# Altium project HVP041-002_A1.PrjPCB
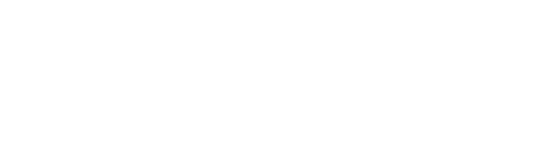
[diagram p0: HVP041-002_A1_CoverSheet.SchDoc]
4 sheets, 106 parts. Net scope: global (net labels, ports and power ports of the same name join across sheets).
Board file: HVP041-002_A1.PcbDoc
Sheets:
  HVP041-002_A1_CoverSheet.SchDoc
  HVP041-002_A1_DC.SchDoc
  HVP041-002_A1_Footprint.SchDoc
  HVP041-002_A1_Hardware.SchDoc

## Sheet HVP041-002_A1_CoverSheet.SchDoc
size 431 x 279 mm; Date: Not shown in title block; ApprovedBy: Not shown in title block; CheckedBy: Not shown in title block; Author: Not shown in title block; CompanyName: Not shown in title block; Engineer: Not shown in title block; Organization: Not shown in title block; Address1: Not shown in title block; Address2: Not shown in title block; Address3: Not shown in title block; Address4: Not shown in title block; DocumentNumber: 1; Revision: Use project parameter SCH_Rev; SheetNumber: 2; SheetTotal: 3; PageSetup: Record=PageOptions¦CenterHorizontal=True¦CenterVertical=True¦PrintScale=1.00¦XCorrection=1.00¦YCorrection=1.00¦PrintKind=0¦BorderSize=5000000¦LeftOffset=0¦BottomOffset=0¦Orientation=2¦PaperLength=1000¦PaperWidth=1000¦Scale=100¦PaperSource=15¦PrintQuality=600¦MediaType=1¦DitherType=10¦PaperKind=Letter¦PrintScaleMode=1

## Sheet HVP041-002_A1_DC.SchDoc
size A2; PageSetup: Record=PageOptions¦CenterHorizontal=True¦CenterVertical=True¦PrintScale=0.69¦XCorrection=1.00¦YCorrection=1.00¦PrintKind=0¦BorderSize=5000000¦LeftOffset=0¦BottomOffset=0¦Orientation=2¦PaperLength=1000¦PaperWidth=1000¦Scale=100¦PaperSource=15¦PrintQuality=600¦MediaType=1¦DitherType=10¦PaperKind=Letter¦PrintScaleMode=1
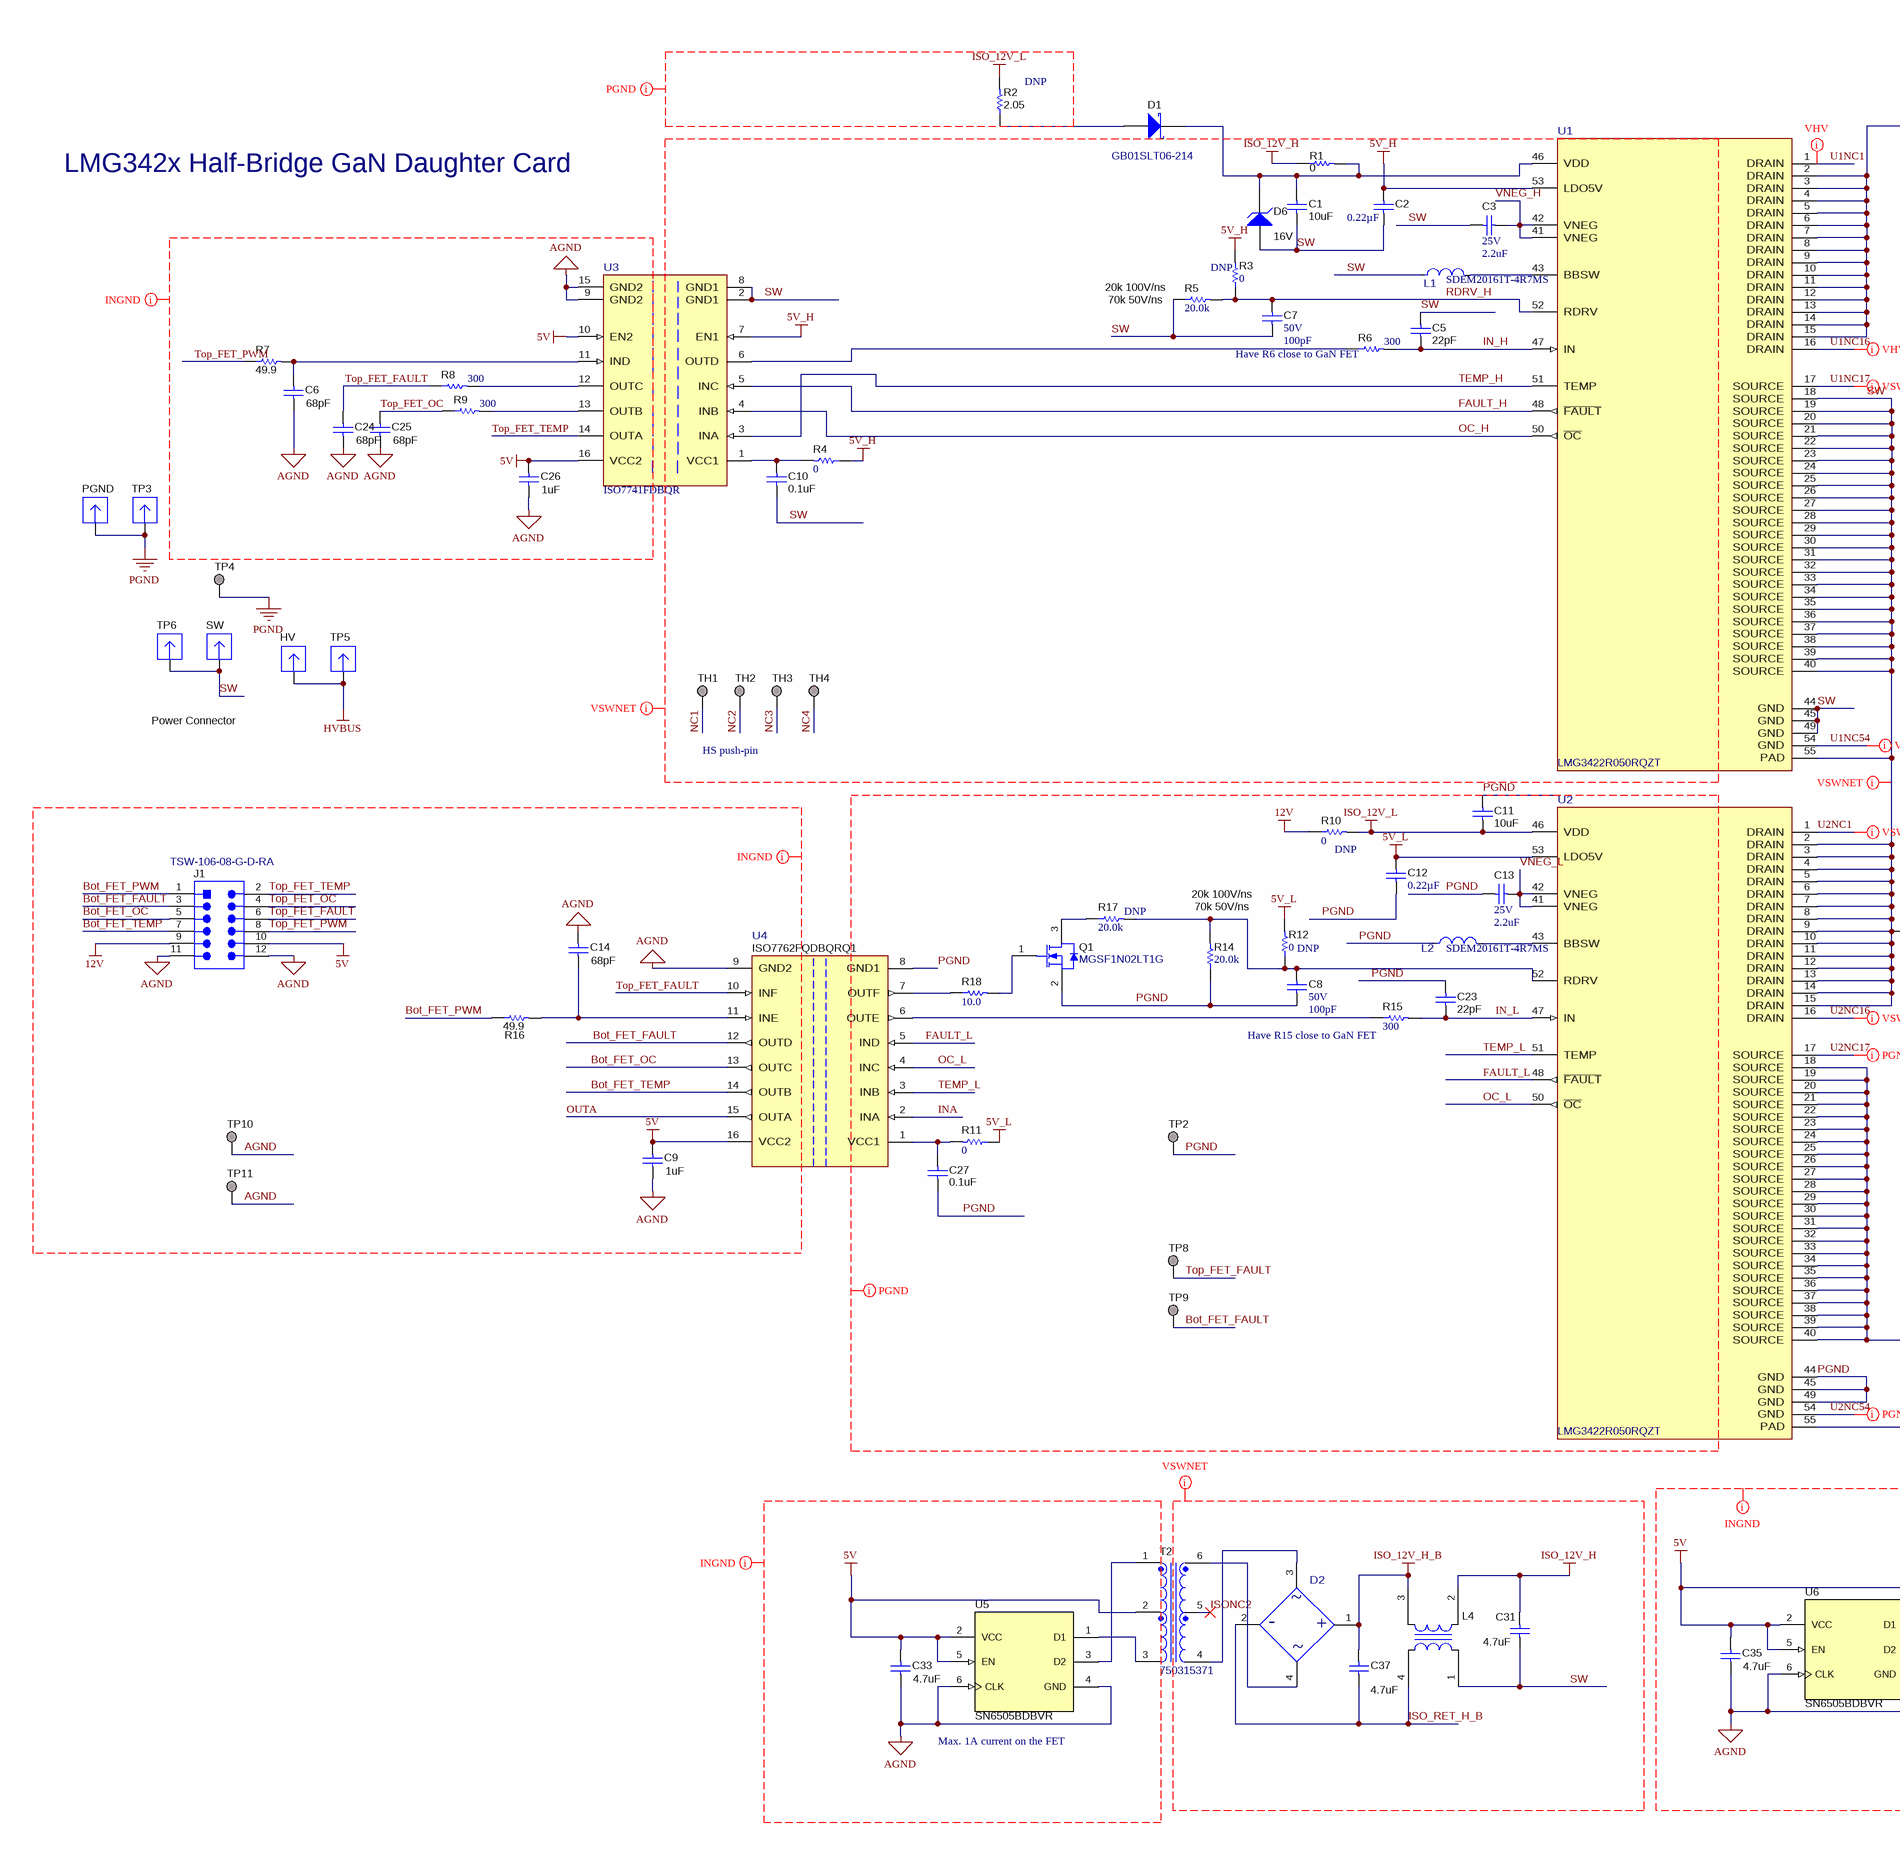
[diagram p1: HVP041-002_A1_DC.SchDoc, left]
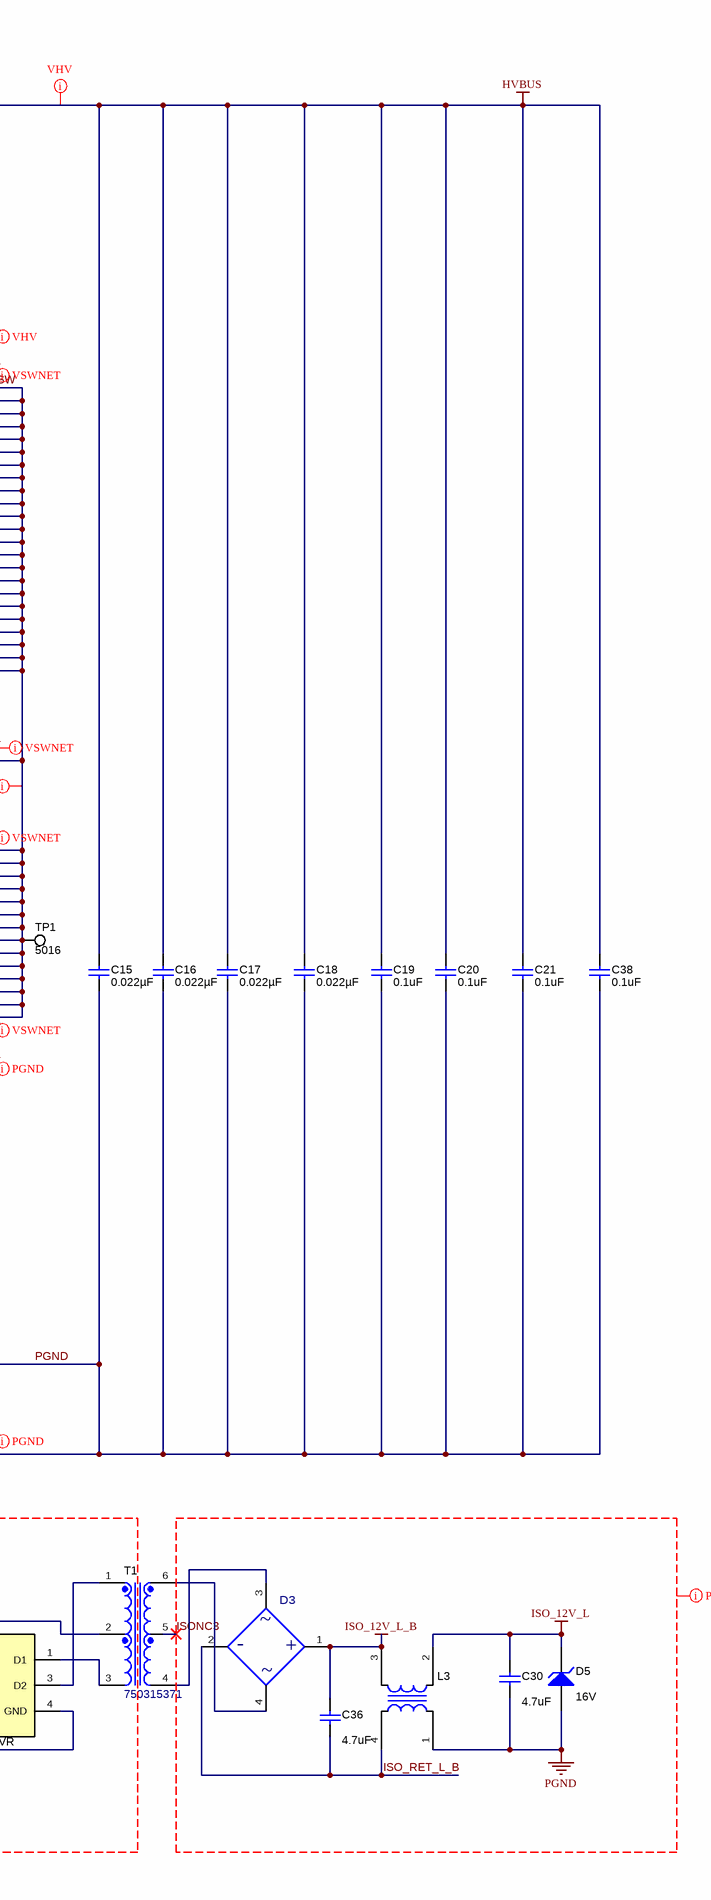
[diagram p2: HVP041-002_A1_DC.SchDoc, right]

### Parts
C1  ValueDisplayed: 10uF  [1206_190]  (hidden comment: C1206C106K3RACTU)
C2  ValueDisplayed: 0.22µF  [0402]  (hidden comment: CL05B224KO5NNNC)
C3  VDC_V: 25V  ValueDisplayed: 2.2uF  [0805_HV]  (hidden comment: GRM219R61E225KA12D)
C5  ValueDisplayed: 22pF  [0402]  (hidden comment: C1005C0G1H220J050BA)
C6  ValueDisplayed: 68pF  [0402]  (hidden comment: C1005C0G1H680J050BA)
C7  VDC_V: 50V  ValueDisplayed: 100pF  [0402]  (hidden comment: 04025A101FAT2A)
C8  VDC_V: 50V  ValueDisplayed: 100pF  [0402]  (hidden comment: 04025A101FAT2A)
C9  ValueDisplayed: 1uF  [0402]  (hidden comment: C1005X5R1E105K050BC)
C10  ValueDisplayed: 0.1uF  [0402]  (hidden comment: C1005X7R1H104K050BB)
C11  ValueDisplayed: 10uF  [1206_190]  (hidden comment: C1206C106K3RACTU)
C12  ValueDisplayed: 0.22µF  [0402]  (hidden comment: CL05B224KO5NNNC)
C13  VDC_V: 25V  ValueDisplayed: 2.2uF  [0805_HV]  (hidden comment: GRM219R61E225KA12D)
C14  ValueDisplayed: 68pF  [0402]  (hidden comment: C1005C0G1H680J050BA)
C15  ValueDisplayed: 0.022µF  [1206_190]  (hidden comment: C1206C223KDRACTU)
C16  ValueDisplayed: 0.022µF  [1206_190]  (hidden comment: C1206C223KDRACTU)
C17  ValueDisplayed: 0.022µF  [1206_190]  (hidden comment: C1206C223KDRACTU)
C18  ValueDisplayed: 0.022µF  [1206_190]  (hidden comment: C1206C223KDRACTU)
C19  ValueDisplayed: 0.1uF  [1812_254]  (hidden comment: C1812W104KDRACTU)
C20  ValueDisplayed: 0.1uF  [1812_254]  (hidden comment: C1812W104KDRACTU)
C21  ValueDisplayed: 0.1uF  [1812_254]  (hidden comment: C1812W104KDRACTU)
C23  ValueDisplayed: 22pF  [0402]  (hidden comment: C1005C0G1H220J050BA)
C24  ValueDisplayed: 68pF  [0402]  (hidden comment: C1005C0G1H680J050BA)
C25  ValueDisplayed: 68pF  [0402]  (hidden comment: C1005C0G1H680J050BA)
C26  ValueDisplayed: 1uF  [0402]  (hidden comment: C1005X5R1E105K050BC)
C27  ValueDisplayed: 0.1uF  [0402]  (hidden comment: C1005X7R1H104K050BB)
C30  ValueDisplayed: 4.7uF  [0603]  (hidden comment: C1608X5R1V475K080AC)
C31  ValueDisplayed: 4.7uF  [0603]  (hidden comment: C1608X5R1V475K080AC)
C33  ValueDisplayed: 4.7uF  [0805_HV]  (hidden comment: GCM21BR71C475KA73L)
C35  ValueDisplayed: 4.7uF  [0805_HV]  (hidden comment: GCM21BR71C475KA73L)
C36  ValueDisplayed: 4.7uF  [0603]  (hidden comment: C1608X5R1V475K080AC)
C37  ValueDisplayed: 4.7uF  [0603]  (hidden comment: C1608X5R1V475K080AC)
C38  ValueDisplayed: 0.1uF  [1812_254]  (hidden comment: C1812W104KDRACTU)
D1  GB01SLT06-214  [SMB]
D2  KMB23STR  [FP-KMB23STR_SMT_4MM725_3MM85-MFG]  (value not drawn)
D3  KMB23STR  [FP-KMB23STR_SMT_4MM725_3MM85-MFG]  (value not drawn)
D5  value 16V  [SOD-123]  (hidden comment: BZT52C16-7-F)
D6  value 16V  [SOD-123]  (hidden comment: BZT52C16-7-F)
HV  3621-0-32-15-00-00-08-0  [Mill-Max_3621-0-32-xx-00-00-08-0]  (value not drawn)
J1  TSW-106-08-G-D-RA  [AB12-DEST]
L1  SDEM20161T-4R7MS  [FP-SDEM20161T-4R7MS_SMD2-MFG]  (value not drawn)
L2  SDEM20161T-4R7MS  [FP-SDEM20161T-4R7MS_SMD2-MFG]  (value not drawn)
L3  ACM2520-601-2P-T002  [TDK_ACM2520-2P]  (value not drawn)
L4  ACM2520-601-2P-T002  [TDK_ACM2520-2P]  (value not drawn)
PGND  3621-0-32-15-00-00-08-0  [Mill-Max_3621-0-32-xx-00-00-08-0]  (value not drawn)
Q1  MGSF1N02LT1G  [SOT-23]
R1  ValueDisplayed: 0  [0603]  (hidden comment: MCT06030Z0000ZP500)
R2  ValueDisplayed: 2.05  [1206]  (hidden comment: CRCW12062R05FKEA)
R3  ValueDisplayed: 0  [0402]  (hidden comment: MCR01MZPJ000)  (no BOM)
R4  ValueDisplayed: 0  [0402]  (hidden comment: MCR01MZPJ000)
R5  ValueDisplayed: 20.0k  [0402]  (hidden comment: CRCW040220K0FKED)
R6  ValueDisplayed: 300  [0402]  (hidden comment: CRCW0402300RJNED)
R7  ValueDisplayed: 49.9  [0402]  (hidden comment: RC0402FR-0749R9L)
R8  ValueDisplayed: 300  [0402]  (hidden comment: CRCW0402300RJNED)
R9  ValueDisplayed: 300  [0402]  (hidden comment: CRCW0402300RJNED)
R10  ValueDisplayed: 0  [1206]  (hidden comment: ERJ-8GEY0R00V)  (no BOM)
R11  ValueDisplayed: 0  [0402]  (hidden comment: MCR01MZPJ000)
R12  ValueDisplayed: 0  [0402]  (hidden comment: MCR01MZPJ000)  (no BOM)
R14  ValueDisplayed: 20.0k  [0402]  (hidden comment: CRCW040220K0FKED)
R15  ValueDisplayed: 300  [0402]  (hidden comment: CRCW0402300RJNED)
R16  ValueDisplayed: 49.9  [0402]  (hidden comment: RC0402FR-0749R9L)
R17  ValueDisplayed: 20.0k  [0402]  (hidden comment: CRCW040220K0FKED)  (no BOM)
R18  ValueDisplayed: 10.0  [0402]  (hidden comment: CRCW040210R0FKED)
SW  3621-0-32-15-00-00-08-0  [Mill-Max_3621-0-32-xx-00-00-08-0]  (value not drawn)
T1  750315371  [Wurth_750315371]
T2  750315371  [Wurth_750315371]
TH1  (no value)  [TP_H045P075]  (no BOM)
TH2  (no value)  [TP_H045P075]  (no BOM)
TH3  (no value)  [TP_H045P075]  (no BOM)
TH4  (no value)  [TP_H045P075]  (no BOM)
TP1  5016  [Testpoint_Keystone_Compact]
TP2  (no value)  [TESTPOINT]
TP3  3621-0-32-15-00-00-08-0  [Mill-Max_3621-0-32-xx-00-00-08-0]  (value not drawn)
TP4  (no value)  [Harwin_S2751-46R]
TP5  3621-0-32-15-00-00-08-0  [Mill-Max_3621-0-32-xx-00-00-08-0]  (value not drawn)
TP6  3621-0-32-15-00-00-08-0  [Mill-Max_3621-0-32-xx-00-00-08-0]  (value not drawn)
TP8  (no value)  [TESTPOINT]
TP9  (no value)  [TESTPOINT]
TP10  (no value)  [TESTPOINT]
TP11  (no value)  [TESTPOINT]
U1  LMG3422R050RQZT  [RQZ0054A-MFG-NV]
U2  LMG3422R050RQZT  [RQZ0054A-MFG-NV]
U3  ISO7741FDBQR  [DBQ0016A-MFG]
U4  ISO7762FQDBQRQ1  [DBQ0016A-MFG]
U5  SN6505BDBVR  [DBV0006A_N]
U6  SN6505BDBVR  [DBV0006A_N]

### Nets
5V: C9.1 C26.1 C33.1 C35.1 J1.10 T1.2 T2.2 U3.10(EN2) U3.16(VCC2) U4.16(VCC2) U5.2(VCC) U5.5(EN) U6.2(VCC) U6.5(EN)
5V_H: C2.1 R3.2 R4.1 U1.53(LDO5V) U3.7(EN1)
5V_L: C12.1 R11.1 R12.2 U2.53(LDO5V)
12V: J1.9 R10.1
AGND: C6.2 C9.2 C14.1 C24.2 C25.2 C26.2 C33.2 C35.2 J1.11 J1.12 TP10.1 TP11.1 U3.9(GND2) U3.15(GND2) U4.9(GND2) U5.4(GND) U5.6(CLK) U6.4(GND) U6.6(CLK)
HVBUS: C15.1 C16.1 C17.1 C18.1 C19.1 C20.1 C21.1 C38.1 HV.1 TP5.1 U1.2(DRAIN) U1.3(DRAIN) U1.4(DRAIN) U1.5(DRAIN) U1.6(DRAIN) U1.7(DRAIN) U1.8(DRAIN) U1.9(DRAIN) U1.10(DRAIN) U1.11(DRAIN) U1.12(DRAIN) U1.13(DRAIN) U1.14(DRAIN) U1.15(DRAIN)
ISO_12V_H: C31.1 L4.2 R1.1
ISO_12V_H_B: C37.1 D2.1(+) L4.3
ISO_12V_L: C11.2 C30.1 D5.1(K) L3.2 R2.2 R10.2 U2.46(VDD)
ISO_12V_L_B: C36.1 D3.1(+) L3.3
PGND: C8.2 C11.1 C12.2 C13.2 C15.2 C16.2 C17.2 C18.2 C19.2 C20.2 C21.2 C23.1 C27.2 C30.2 C38.2 D5.2(A) L2.1 L3.1 PGND.1 Q1.2(S) R14.1 TP2.1 TP3.1 TP4.1 U2.18(SOURCE) U2.19(SOURCE) U2.20(SOURCE) U2.21(SOURCE) U2.22(SOURCE) U2.23(SOURCE) U2.24(SOURCE) U2.25(SOURCE) U2.26(SOURCE) U2.27(SOURCE) U2.28(SOURCE) U2.29(SOURCE) U2.30(SOURCE) U2.31(SOURCE) U2.32(SOURCE) U2.33(SOURCE) U2.34(SOURCE) U2.35(SOURCE) U2.36(SOURCE) U2.37(SOURCE) U2.38(SOURCE) U2.39(SOURCE) U2.40(SOURCE) U2.44(GND) U2.45(GND) U2.49(GND) U2.55(PAD) U4.8(GND1)
Bot_FET_FAULT: J1.3 TP9.1 U4.12(OUTD)
Bot_FET_OC: J1.5 U4.13(OUTC)
Bot_FET_PWM: J1.1 R16.1
Bot_FET_TEMP: J1.7 U4.14(OUTB)
FAULT_H: U1.48(~{FAULT}) U3.5(INC)
FAULT_L: U2.48(~{FAULT}) U4.5(IND)
IN_H: C5.2 R6.2 U1.47(IN)
IN_L: C23.2 R15.2 U2.47(IN)
INA: U4.2(INA)
ISO_RET_H_B: C37.2 D2.2(-) L4.4
ISO_RET_L_B: C36.2 D3.2(-) L3.4
ISONC2: T2.5
ISONC3: T1.5
NC1: TH1.1
NC2: TH2.1
NC3: TH3.1
NC4: TH4.1
OC_H: U1.50(~{OC}) U3.4(INB)
OC_L: U2.50(~{OC}) U4.4(INC)
OUTA: U4.15(OUTA)
RDRV_H: C7.1 R3.1 R5.2 U1.52(RDRV)
SW: C1.2 C2.2 C3.2 C5.1 C7.2 C10.2 C31.2 D6.2(A) L1.1 L4.1 R5.1 SW.1 TP1.1 TP6.1 U1.18(SOURCE) U1.19(SOURCE) U1.20(SOURCE) U1.21(SOURCE) U1.22(SOURCE) U1.23(SOURCE) U1.24(SOURCE) U1.25(SOURCE) U1.26(SOURCE) U1.27(SOURCE) U1.28(SOURCE) U1.29(SOURCE) U1.30(SOURCE) U1.31(SOURCE) U1.32(SOURCE) U1.33(SOURCE) U1.34(SOURCE) U1.35(SOURCE) U1.36(SOURCE) U1.37(SOURCE) U1.38(SOURCE) U1.39(SOURCE) U1.40(SOURCE) U1.44(GND) U1.45(GND) U1.49(GND) U1.55(PAD) U2.2(DRAIN) U2.3(DRAIN) U2.4(DRAIN) U2.5(DRAIN) U2.6(DRAIN) U2.7(DRAIN) U2.8(DRAIN) U2.9(DRAIN) U2.10(DRAIN) U2.11(DRAIN) U2.12(DRAIN) U2.13(DRAIN) U2.14(DRAIN) U2.15(DRAIN) U3.2(GND1) U3.8(GND1)
TEMP_H: U1.51(TEMP) U3.3(INA)
TEMP_L: U2.51(TEMP) U4.3(INB)
Top_FET_FAULT: C24.1 J1.6 R8.1 TP8.1 U4.10(INF)
Top_FET_OC: C25.1 J1.4 R9.1
Top_FET_PWM: J1.8 R7.1
Top_FET_TEMP: J1.2 U3.14(OUTA)
U1NC1: U1.1(DRAIN)
U1NC16: U1.16(DRAIN)
U1NC17: U1.17(SOURCE)
U1NC54: U1.54(GND)
U2NC1: U2.1(DRAIN)
U2NC16: U2.16(DRAIN)
U2NC17: U2.17(SOURCE)
U2NC54: U2.54(GND)
VNEG_H: C3.1 U1.41(VNEG) U1.42(VNEG)
VNEG_L: C13.1 U2.41(VNEG) U2.42(VNEG)
NetC1_1: C1.1 D1.1(K) D6.1(K) R1.2 U1.46(VDD)
NetC6_1: C6.1 R7.2 U3.11(IND)
NetC8_1: C8.1 R12.1 R14.2 R17.2 U2.52(RDRV)
NetC10_1: C10.1 R4.2 U3.1(VCC1)
NetC14_2: C14.2 R16.2 U4.11(INE)
NetC27_1: C27.1 R11.2 U4.1(VCC1)
NetD1_2: D1.2(A) R2.1
NetD2_3: D2.3(1_~) T2.4
NetD2_4: D2.4(2_~) T2.6
NetD3_3: D3.3(1_~) T1.4
NetD3_4: D3.4(2_~) T1.6
NetL1_2: L1.2 U1.43(BBSW)
NetL2_2: L2.2 U2.43(BBSW)
NetQ1_1: Q1.1(G) R18.2
NetQ1_3: Q1.3(D) R17.1
NetR6_1: R6.1 U3.6(OUTD)
NetR8_2: R8.2 U3.12(OUTC)
NetR9_2: R9.2 U3.13(OUTB)
NetR15_1: R15.1 U4.6(OUTE)
NetR18_1: R18.1 U4.7(OUTF)
NetT1_1: T1.1 U6.3(D2)
NetT1_3: T1.3 U6.1(D1)
NetT2_1: T2.1 U5.3(D2)
NetT2_3: T2.3 U5.1(D1)

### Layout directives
net class VSWNET: 5V_H, FAULT_H, IN_H, ISO_12V_H, ISO_12V_H_B, ISO_RET_H_B, ISONC2, NC1, NC2, NC3, NC4, OC_H, RDRV_H, SW, TEMP_H, U1NC17, U1NC54, U2NC1, U2NC16, VNEG_H
net class VHV: HVBUS, U1NC1, U1NC16
net class INGND: 5V, 12V, AGND, Bot_FET_FAULT, Bot_FET_OC, Bot_FET_PWM, Bot_FET_TEMP, OUTA, Top_FET_FAULT, Top_FET_OC, Top_FET_PWM, Top_FET_TEMP
net class PGND: 5V_L, 12V, Bot_FET_FAULT, FAULT_L, IN_L, INA, ISO_12V_L, ISO_12V_L_B, ISO_RET_L_B, ISONC3, OC_L, PGND, TEMP_L, Top_FET_FAULT, U2NC17, U2NC54, VNEG_L

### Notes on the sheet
- (near R2) DNP
- LMG342x Half-Bridge GaN Daughter Card
- (near R5) 20k 100V/ns
- (near R5) 70k 50V/ns
- (near R3) DNP
- (near L1) SDEM20161T-4R7MS
- (near R6) Have R6 close to GaN FET
- Power Connector
- HS push-pin
- (near R10) DNP
- (near R17) DNP
- 20k 100V/ns
- 70k 50V/ns
- (near R12) DNP
- (near L2) SDEM20161T-4R7MS
- (near R15) Have R15 close to GaN FET
- Max. 1A current on the FET

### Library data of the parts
C1 C11 = CMP-0008589-2: CAP, CERM, 10 uF, 25 V, +/- 10%, X7R, 1206_190; Manufacturer: Kemet; Polarized: N; Value: 10uF; U/M: EA; Cap_F: 10µF; Value1: Unknown; VDC_V: 25V; TaMin_C: -55°C; TaMax_C: 125°C; Cap_Case: 1206; SizeArea_mm2: 5.12; SizeAreaWB_mm2: 10.92; SizeX_mm: 3.2; SizeY_mm: 1.6; SizeZ_mm: 1.9; AEC Category: Q200
C2 C12 = CMP-0860563-1: CAP, CERM, 0.22 µF, 16 V,+/- 10%, X7R, 0402; Manufacturer: Samsung Electro-Mechanics; SizeX_mm: 1; Green_REACh: Incomplete; TaMin_C: -55°C; SizeArea_mm2: 0.5; TaMax_C: 125°C; U/M: EA; Green_Lifecycle: Active; SizeAreaWB_mm2: 3; VDC_V: 16V; AEC Qualified: N; SizeZ_mm: 0.6; AEC Category: Q200; Cap_F: 220nF; Value: 0.22uF
C3 C13 = CMP-0008208-1: CAP, CERM, 2.2 uF, 25 V, +/- 10%, X5R, 0805; Manufacturer: MuRata; TaMin_C: -55°C; ESR_ohm: 6m; Polarized: N; SizeAreaWB_mm2: 6.75; Value1: 0.006 ohm; U/M: EA; Value: 2.2uF; TaMax_C: 85°C; SizeZ_mm: 1.45; SizeX_mm: 2; SizeY_mm: 1.25; Cap_Case: 0805; SizeArea_mm2: 2.5; Cap_F: 2.2µF; AEC Category: Q200
C5 C23 = CMP-0006248-2: CAP, CERM, 22 pF, 50 V, +/- 5%, C0G/NP0, 0402; Manufacturer: TDK; Alternate PartNumber: CGA2B2NP01H220J050BA; Polarized: N; Value: 22pF; U/M: EA; Value1: Unknown; VDC_V: 50V; TaMin_C: -55°C; TaMax_C: 125°C; AEC Category: Q200; SizeArea_mm2: 0.5; SizeAreaWB_mm2: 3; SizeX_mm: 1; SizeZ_mm: 0.6
C6 C14 C24 C25 = CMP-0006251-2: CAP, CERM, 68 pF, 50 V, +/- 5%, C0G/NP0, 0402; Manufacturer: TDK; Alternate Manufacturer: Murata; Alternate PartNumber: GRM1555C1H680JA01D; TaMin_C: -55°C; Polarized: N; SizeAreaWB_mm2: 3; Value1: Unknown; U/M: EA; Value: 68pF; TaMax_C: 125°C; SizeZ_mm: 0.6; SizeX_mm: 1; SizeY_mm: 0.5; Value2: 50V; AEC Category: Q200
C7 C8 = CMP-0006196-2: CAP, CERM, 100 pF, 50 V, +/- 1%, C0G/NP0, 0402; Manufacturer: AVX; TaMin_C: -55°C; Polarized: N; SizeAreaWB_mm2: 3; Value1: Unknown; U/M: EA; Value: 100pF; TaMax_C: 125°C; SizeZ_mm: 0.6; SizeX_mm: 1; SizeY_mm: 0.5; AEC Category: Q200
C9 C26 = CMP-0006276-2: CAP, CERM, 1 uF, 25 V, +/- 10%, X5R, 0402; Manufacturer: TDK; Alternate PartNumber: C1005X5R1E225K050BC; TaMin_C: -55°C; Polarized: N; SizeAreaWB_mm2: 3; Value1: Unknown; U/M: EA; Value: 1uF; TaMax_C: 80°C; SizeZ_mm: 0.6; SizeX_mm: 1; SizeY_mm: 0.5; Value2: 25V; CompType: Capacitor; Cap_F: 1µF; AEC Category: Q200
C10 C27 = CMP-0006297-2: CAP, CERM, 0.1 uF, 50 V, +/- 10%, X7R, 0402; Manufacturer: TDK; Alternate PartNumber: 885012205037; Alternate Manufacturer: Wurth Elektronik; Polarized: N; Value: 0.1uF; U/M: EA; Cap_F: 100nF; ESR_ohm: 0.039064; Value1: 0.039064 ohm; VDC_V: 50V; IRMS_A: 8.14669dA; TaMin_C: -55°C; TaMax_C: 125°C; SizeArea_mm2: 0.5; SizeAreaWB_mm2: 3; SizeX_mm: 1; SizeZ_mm: 0.6; AEC Category: Q200
C15-C18 = CMP-0084048-1: CAP, CERM, 0.022 µF, 1000 V,+/- 10%, X7R, AEC-Q200 Grade 1, 1206; Manufacturer: Kemet; Polarized: N; CompType: Capacitor; Value: 0.022uF; U/M: EA; Cap_F: 22nF; VDC_V: 1kV; Value2: 1000V; TaMin_C: -55°C; TaMax_C: 125°C; Cap_Case: 1206; SizeArea_mm2: 5.12; SizeAreaWB_mm2: 10.92; SizeX_mm: 3.2; SizeY_mm: 1.6; SizeZ_mm: 1.9; AEC Category: Q200; AEC Qualified: Y; AEC Grade: 1
C19-C21 C38 = CMP-0009326-2: CAP, CERM, 0.1 uF, 1000 V, +/- 10%, X7R, 1812; Manufacturer: Kemet; Polarized: N; Value: 0.1uF; U/M: EA; Cap_F: 100nF; Value1: Unknown; VDC_V: 1kV; Value2: 1000V; TaMin_C: -55°C; TaMax_C: 125°C; Cap_Case: 1812; AEC Category: Q200; SizeArea_mm2: 14.4; SizeAreaWB_mm2: 23.1; SizeX_mm: 4.5; SizeY_mm: 3.2; SizeZ_mm: 2.54
C30 C31 C36 = CMP-0007022-5: CAP, CERM, 4.7 uF, 35 V, +/- 10%, X5R, 0603; Manufacturer: TDK; TaMin_C: -55°C; ESR_ohm: 3.728m; Polarized: N; SizeAreaWB_mm2: 4.68; Value1: 0.003728 ohm; U/M: EA; Value: 4.7uF; TaMax_C: 85°C; SizeZ_mm: 1; SizeX_mm: 1.6; SizeY_mm: 0.8; Value2: 35V; SizeArea_mm2: 1.28; Cap_F: 4.7µF; IRMS_A: 2.69359A; AEC Category: Q200
C33 C35 = CMP-0008020-2: CAP, CERM, 4.7 uF, 16 V, +/- 10%, X7R, AEC-Q200 Grade 1, 0805; Manufacturer: MuRata; TaMin_C: -55°C; Polarized: N; SizeAreaWB_mm2: 6.75; Value1: Unknown; U/M: EA; Value: 4.7uF; TaMax_C: 125°C; SizeZ_mm: 1.45; SizeX_mm: 2; SizeY_mm: 1.25; Cap_Case: 0805; Value2: 16V; SizeArea_mm2: 2.5; AEC Qualified: Y; Cap_F: 4.7µF; AEC Grade: 1; AEC Category: Q200
C37 = CMP-0007022-5: CAP, CERM, 4.7 uF, 35 V, +/- 10%, X5R, 0603; Manufacturer: TDK; TaMin_C: -55°C; ESR_ohm: 3.728m; Polarized: N; SizeAreaWB_mm2: 4.68; Value1: 0.003728 ohm; U/M: EA; Value: 4.7uF; TaMax_C: 85°C; SizeZ_mm: 1; SizeX_mm: 1.6; SizeY_mm: 0.8; Value2: 35V; SizeArea_mm2: 1.28; CompType: Capacitor; Cap_F: 4.7µF; IRMS_A: 2.69359A; AEC Category: Q200
D1 = CMP-0076998-2: Diode, Schottky, 650 V, 1 A, SMB; Manufacturer: GeneSiC Semiconductor; Value1: 1A; SizeZ_mm: 2.6; Value: 650V; SizeAreaWB_mm2: 44.156; TJmax_C: 175°C; RJC_CperW: 3.55; SizeArea_mm2: 21.336; AEC Category: Q101; Value2: 2V; SizeY_mm: 3.81; SizeX_mm: 5.6
D2 D3 = CMP-0089345-2: Bridge Rectifier Single Phase Schottky 30V Surface Mount MBS; Manufacturer: SMC; TJmax_C: 150°C; Cap_F: 28pF; Max Surge Forward Current: 50A; Forward Current: 2A; Peak Reverse Current: 0.1mA; CompType: Diode; Standoff Height: 0.2mm; AEC Category: Q101; SizeZ_mm: 2.9mm; AEC Qualified: No
D5 D6 = CMP-0005769-2: Diode, Zener, 16 V, 500 mW, AEC-Q101, SOD-123; Manufacturer: Diodes Inc.; Power_W: 500mW; SizeAreaWB_mm2: 13.095; Value1: 0.5W; RJA_CperW: 338; U/M: EA; SizeZ_mm: 1.35; SizeX_mm: 3.85; SizeY_mm: 1.7; SizeArea_mm2: 6.545; AEC Qualified: Y; AEC Category: Q101
HV PGND SW TP3 TP5 TP6 = CMP-0082316-1: Manufacturer: Mill-Max; CompType: PCB Pin; ContactFinish: Gold; Gender: Male; Row_Count: 1
J1 = CMP-0075414-2: Header, 100mil, 6x2, Gold, R/A, TH; Manufacturer: Samtec; Pitch_mm: 2.54; Cert_VDE: N; Gender: Male; Cert_CSA: Y; Current_A: 6.3A; Voltage_V: 550V; Row_Count: 2
L1 L2 = CMP-0089347-1: 4.7µH Unshielded Inductor 1.1A 426mOhm Max 0806 (2016 Metric); Manufacturer: Cyntec; AEC Qualified: No; Material: Metal Dust; Isat: 1.26A; Test Frequency: 1MHz; DCR_ohm: 0.426; SizeZ_mm: 1mm; Tolerance_%: 20%
L3 L4 = CMP-0013161-2: Coupled inductor, 0.2 A, 0.45 ohm, SMD; Manufacturer: TDK; DCR_ohm: 4.5d; SizeAreaWB_mm2: 10.5; SizeArea_mm2: 5; SizeX_mm: 2.5; SizeY_mm: 2; SizeZ_mm: 1.3
Q1 = CMP-0000221-1: MOSFET, N-CH, 20 V, 0.75 A, SOT-23; Alternate Manufacturer: None; Manufacturer: ON Semiconductor; SizeZ_mm: 1.1; ChType: N; Value2: 6 nC; Value1: 0.1; VdsMax_V: 20V; SizeX_mm: 2.5; SizeY_mm: 3; Value: 20V; Rdson45_ohm: 0.13; SizeArea_mm2: 7.5; AEC Category: Q101; IdsMax_A: 750mA; SizeAreaWB_mm2: 14; U/M: EA; QgTyp_nC: 6
R1 = CMP-0025884-3: RES, 0, 5%, 0.125 W, 0603; Manufacturer: Vishay/Beyschlag; Power_W: 125mW; TempCo: ppm/C; Value_Code: 0000; U/M: EA; Value: 0; EIA_Code: E24; SizeX_mm: 1.6; SizeY_mm: 0.8; SizeZ_mm: 1; Value2: 0.125W; SizeArea_mm2: 1.28; CompType: Resistor; AEC Qualified: N; AEC Category: Q200
R2 = CMP-0016879-3: RES, 2.05, 1%, 0.25 W, AEC-Q200 Grade 0, 1206; Manufacturer: Vishay-Dale; Power_W: 250mW; TempCo: 100 ppm/C; Value_Code: 2R05; Value: 2.05; EIA_Code: E96; SizeX_mm: 3.2; SizeY_mm: 1.6; SizeZ_mm: 1.35; Value2: 0.25W; SizeArea_mm2: 5.12; AEC Qualified: Y; VDC_V: 200V; AEC Category: Q200; AEC Grade: 0
R3 R4 R11 R12 = CMP-0027002-2: RES, 0, 5%, 0.063 W, 0402; Manufacturer: Rohm; Power_W: 63mW; TempCo: 500 ppm/C; Value_Code: 0000; U/M: EA; Value: 0; EIA_Code: E24; SizeX_mm: 1; SizeY_mm: 0.5; SizeZ_mm: 0.6; Value2: 0.063W; VDC_V: 50V; AEC Category: Q200
R5 R14 R17 = CMP-0026162-1: RES, 20.0 k, 1%, 0.063 W, 0402; Manufacturer: Vishay-Dale; Power_W: 63mW; TempCo: 100 ppm/C; Value_Code: 20k0; U/M: EA; Value: 20.0k; EIA_Code: E96; Res_ohm: 20k; SizeX_mm: 1; SizeY_mm: 0.5; SizeZ_mm: 0.6; Value2: 0.063W; VDC_V: 50V; AEC Category: Q200
R6 R8 R9 R15 = CMP-0026902-3: RES, 300, 5%, 0.063 W, AEC-Q200 Grade 0, 0402; Manufacturer: Vishay-Dale; Power_W: 63mW; TempCo: 200 ppm/C; Value_Code: 300R; Value: 300; EIA_Code: E24; SizeX_mm: 1; SizeY_mm: 0.5; SizeZ_mm: 0.6; Value2: 0.063W; AEC Qualified: Y; VDC_V: 50V; AEC Category: Q200; AEC Grade: 0
R7 R16 = CMP-0026738-1: RES, 49.9, 1%, 0.063 W, 0402; Manufacturer: Yageo America; Value: 49.9; Value_Code: 49R9; Power_W: 63mW; Value2: 0.063W; VDC_V: 50V; TempCo: 100 ppm/C; EIA_Code: E96; U/M: EA; AEC Category: Q200; AEC Qualified: N; SizeArea_mm2: 0.5; SizeX_mm: 1; SizeZ_mm: 0.6
R10 = CMP-0018748-3: RES, 0, 5%, 0.25 W, AEC-Q200 Grade 0, 1206; Manufacturer: Panasonic; Power_W: 250mW; TempCo: 600 ppm/C; Value_Code: 0000; Value: 0; EIA_Code: E24; SizeX_mm: 3.2; SizeY_mm: 1.6; SizeZ_mm: 1.35; Value2: 0.25W; SizeArea_mm2: 5.12; AEC Qualified: Y; VDC_V: 200V; AEC Category: Q200; SizeAreaWB_mm2: 10.92
R18 = CMP-0025963-3: RES, 10.0, 1%, 0.063 W, AEC-Q200 Grade 0, 0402; Manufacturer: Vishay-Dale; Power_W: 63mW; TempCo: 100 ppm/C; Value_Code: 10R0; Value: 10.0; EIA_Code: E96; Res_ohm: 10; SizeX_mm: 1; SizeY_mm: 0.5; SizeZ_mm: 0.6; Value2: 0.063W; AEC Qualified: Y; VDC_V: 50V; AEC Category: Q200; AEC Grade: 0
T1 T2 = CMP-0030623-1: Transformer, 105uH, TH; Manufacturer: Wurth Elektronik; Green_Lifecycle: Active; DCR_ohm: 0.06; Green_REACh: Passed; Lp: 105; Ns1toNp: 1.1; Ind_H: 105µH
TH1-TH4 = CMP-0003719-1: Testpoint; Manufacturer: Texas Instruments; Key: TP_H0.45P0.75; CompType: Pad
TP1 = CMP-0055153-1: Test Point, Compact, SMT; Manufacturer: Keystone; CNHeader: FALSE; Green_Lifecycle: Active; Green_REACh: Passed; CT: TRUE
TP2 TP8-TP11 = CMP-0078143-2: TEST POINT.  No entry in BOM.
TP4 = CMP-0003968-1: Test Point, SMT; Manufacturer: Harwin; Key: S2751-46R
U1 U2 = CMP-0088545-3: 600-V 50-mΩ Integrated GaN Power Stage with Smart Driver; Manufacturer: Texas Instruments; Standoff Height: 0mm; TJmax_C: +125°C; Number Of Outputs: 1; Nominal Supply Current: 13mA; Max Supply Voltage: 18V; Min Supply Voltage: 7.5V; SizeZ_mm: 0.9mm; Output Voltage: 480V; AEC Qualified: No; AEC Category: Q200; CompType: IC
U3 = CMP-0089510-1: Manufacturer: Texas Instruments; Nominal Supply Current: 0.8-18mA; SizeZ_mm: 1.75mm; TJmax_C: +150°C; TaMax_C: +125°C; Min Supply Voltage: 2.25V; TaMin_C: -55°C; AEC Qualified: No; Standoff Height: 0.11mm; Max Supply Voltage: 5.5V
U4 = CMP-0091060-1: Automotive, robust EMC, six-channel, 4/2, reinforced digital isolator 16-SSOP -40 to 125; Manufacturer: Texas Instruments; AEC Qualified: Yes; AEC Grade: Grade 1; Standoff Height: 0.11mm; Min Supply Voltage: 2.25V; SizeZ_mm: 1.75mm; TaMax_C: +125°C; Nominal Supply Current: 2.1-25.7mA; TJmax_C: +150°C; Max Supply Voltage: 5.5V; TaMin_C: -40°C
U5 U6 = CMP-0076095-1: Low-Noise 1 A, 420 kHz Transformer Driver, DBV0006A (SOT-23-6); Alternate PartNumber: SN6505BDBVT; Manufacturer: Texas Instruments; SizeArea_mm2: 8.12; SizeAreaWB_mm2: 14.82; SizeX_mm: 2.8; SizeY_mm: 2.9; SizeZ_mm: 1.45; CompType: IC; U/M: EA; Green_Lifecycle: Active; Green_REACh: Passed

## Sheet HVP041-002_A1_Footprint.SchDoc
size 431 x 279 mm; Date: Not shown in title block; ApprovedBy: Not shown in title block; CheckedBy: Not shown in title block; Author: Not shown in title block; CompanyName: Not shown in title block; Engineer: Not shown in title block; Organization: Not shown in title block; Address1: Not shown in title block; Address2: Not shown in title block; Address3: Not shown in title block; Address4: Not shown in title block; DocumentNumber: 1; Revision: Use project parameter SCH_Rev; SheetNumber: 2; SheetTotal: 3; PageSetup: Record=PageOptions¦CenterHorizontal=True¦CenterVertical=True¦PrintScale=1.00¦XCorrection=1.00¦YCorrection=1.00¦PrintKind=0¦BorderSize=5000000¦LeftOffset=0¦BottomOffset=0¦Orientation=2¦PaperLength=1000¦PaperWidth=1000¦Scale=100¦PaperSource=15¦PrintQuality=600¦MediaType=1¦DitherType=10¦PaperKind=Letter¦PrintScaleMode=1
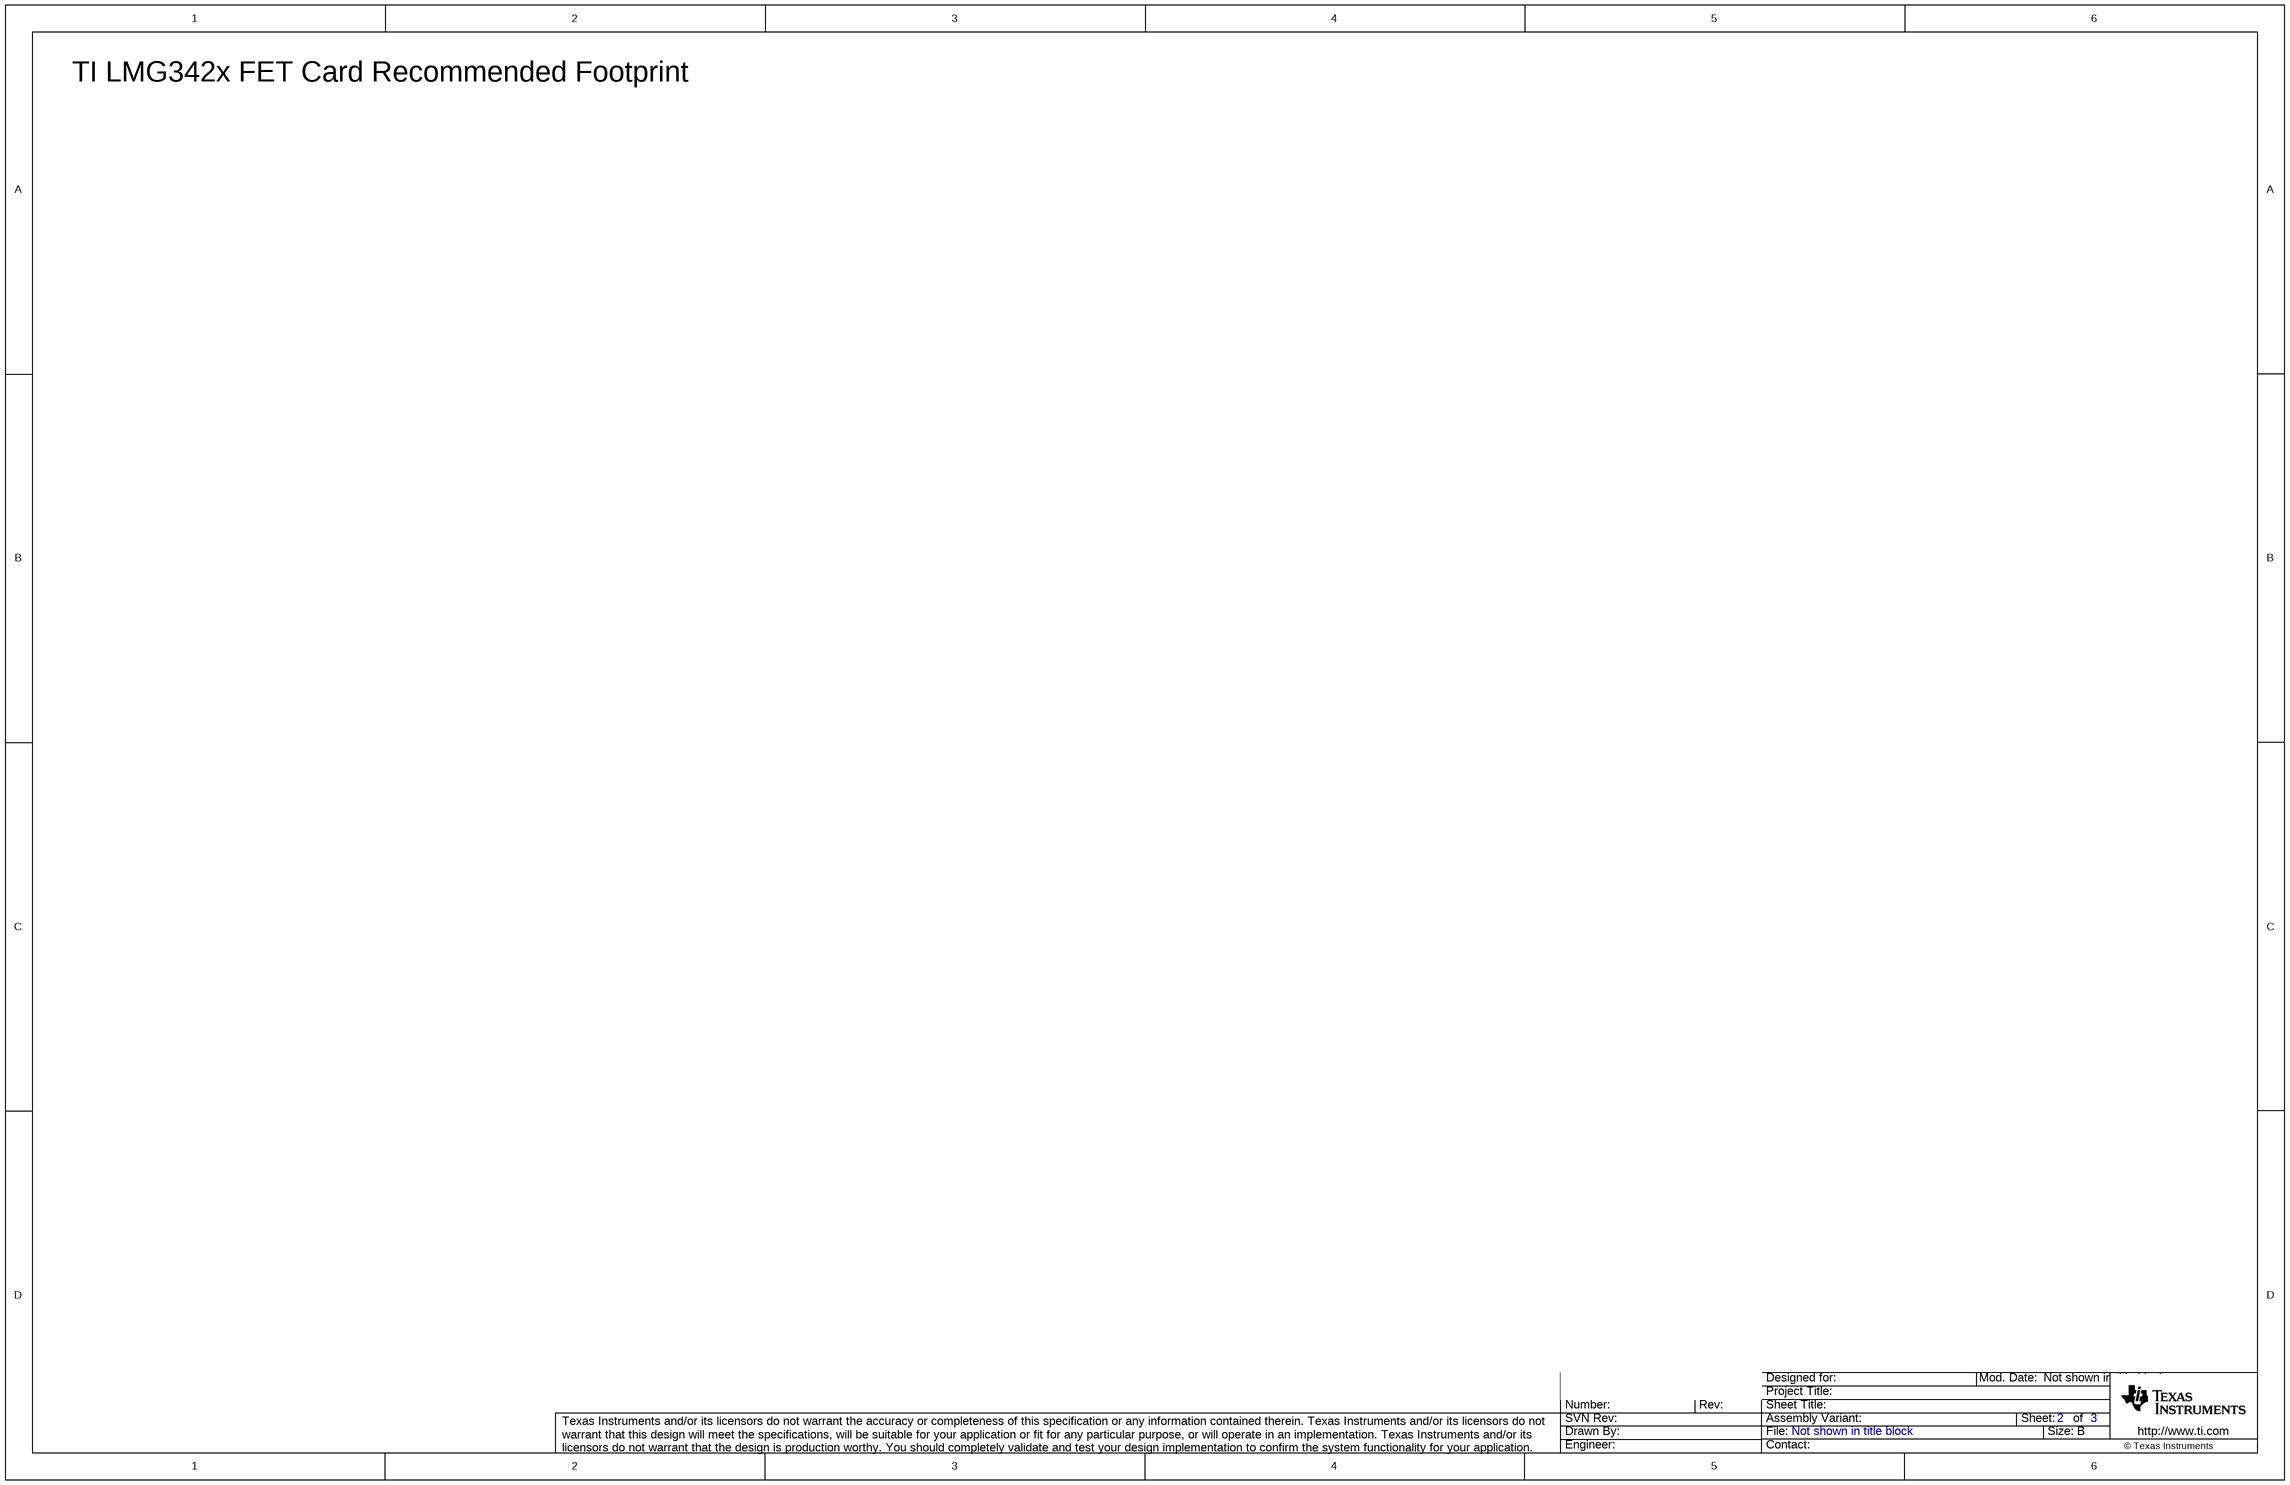
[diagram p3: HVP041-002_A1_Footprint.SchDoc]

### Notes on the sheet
- TI LMG342x FET Card Recommended Footprint

## Sheet HVP041-002_A1_Hardware.SchDoc
size 431 x 279 mm; Date: Not shown in title block; ApprovedBy: Not shown in title block; CheckedBy: Not shown in title block; Author: Not shown in title block; CompanyName: Not shown in title block; Engineer: Not shown in title block; Organization: Not shown in title block; Address1: Not shown in title block; Address2: Not shown in title block; Address3: Not shown in title block; Address4: Not shown in title block; DocumentNumber: 1; Revision: Use project parameter SCH_Rev; SheetNumber: 2; SheetTotal: 3; PageSetup: Record=PageOptions¦CenterHorizontal=True¦CenterVertical=True¦PrintScale=1.00¦XCorrection=1.00¦YCorrection=1.00¦PrintKind=0¦BorderSize=5000000¦LeftOffset=0¦BottomOffset=0¦Orientation=2¦PaperLength=1000¦PaperWidth=1000¦Scale=100¦PaperSource=15¦PrintQuality=600¦MediaType=1¦DitherType=10¦PaperKind=Letter¦PrintScaleMode=1
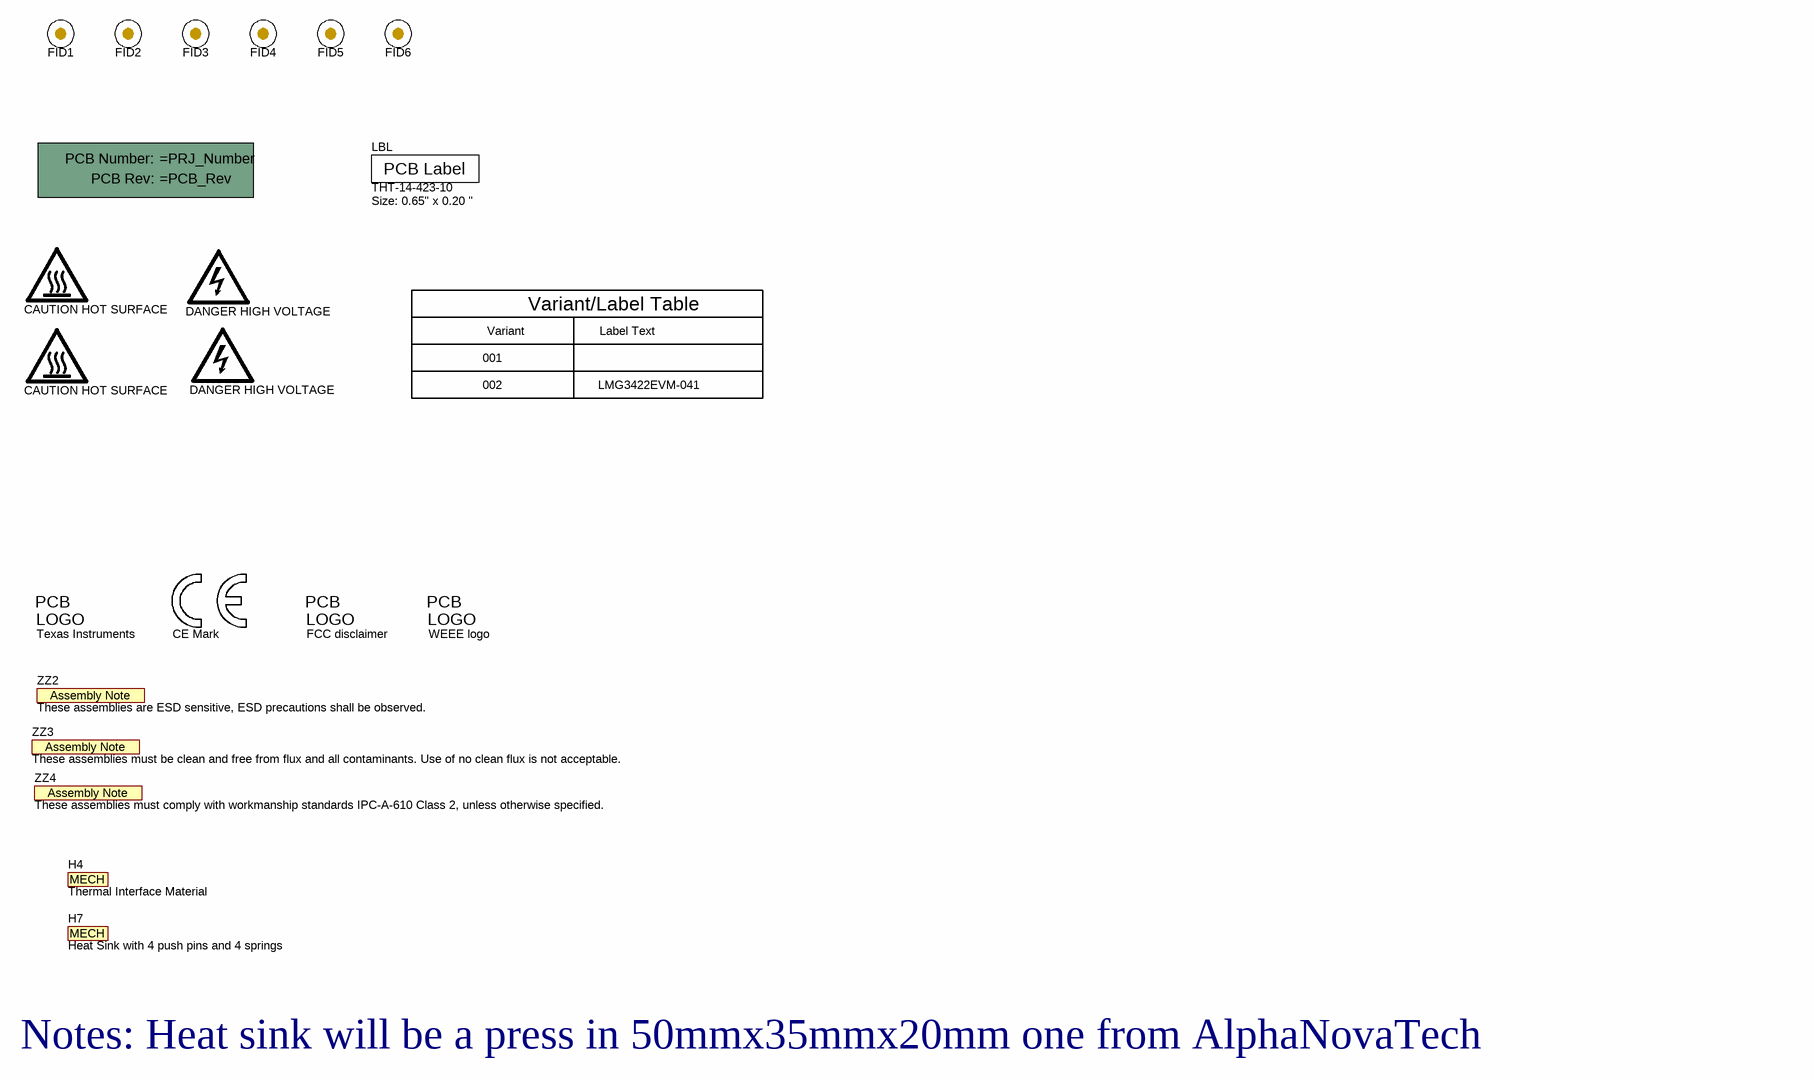
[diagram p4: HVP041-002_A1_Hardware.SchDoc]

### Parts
!PCB1  Printed Circuit Board  (value not drawn)  (mechanical)
FID1  Fiducial  [Fiducial6.4-20]  (value not drawn)
FID2  Fiducial  [Fiducial6.4-20]  (value not drawn)
FID3  Fiducial  [Fiducial6.4-20]  (value not drawn)
FID4  Fiducial  [Fiducial6.4-20]  (value not drawn)
FID5  Fiducial  [Fiducial6.4-20]  (value not drawn)
FID6  Fiducial  [Fiducial6.4-20]  (value not drawn)
H4  Thermal Interface Material  (mechanical)
H7  Heat Sink with 4 push pins and 4 springs  (mechanical)
LBL  THT-14-423-10  Note: Size: 0.65" x 0.20 "  [Label_650x200]
LOGO1  CAUTION HOT SURFACE  [IEC_HotSurface_Small]  (no BOM)
LOGO2  DANGER HIGH VOLTAGE  [IEC_HighVoltage_Small]  (no BOM)
LOGO3  CAUTION HOT SURFACE  [IEC_HotSurface_Small]  (no BOM)
LOGO4  DANGER HIGH VOLTAGE  [IEC_HighVoltage_Small]  (no BOM)
Logo5  CE Mark  [CE_Mark_5mm]  (no BOM)
Logo6  Texas Instruments  [TI_Stacked_Overlay_Small_Vertical]  (no BOM)
Logo7  FCC disclaimer  [FCC_disclaimer_stacked]  (no BOM)
Logo8  WEEE logo  [WEEE_Minimum]  (no BOM)
ZZ2  These assemblies are ESD sensitive, ESD precautions shall be observed.  [AssemblyNote]  (no BOM)
ZZ3  These assemblies must be clean and free from flux and all contaminants. Use of no clean flux is not acceptable.  [AssemblyNote]  (no BOM)
ZZ4  These assemblies must comply with workmanship standards IPC-A-610 Class 2, unless otherwise specified.  [AssemblyNote]  (no BOM)

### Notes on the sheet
- Variant/Label Table
- 001
- Variant
- Label Text
- 002
- LMG3422EVM-041
- Notes: Heat sink will be a press in 50mmx35mmx20mm one from AlphaNovaTech

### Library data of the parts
!PCB1 = CMP-0003618-2: Manufacturer: Any
FID1-FID6 = CMP-0077181-1: Fiducial mark.  There is nothing to buy or mount.
H4 = CMP-0080604-2: Manufacturer: Fuji Polymer Industries; PartNumber: GR80A-0H-50GY; CompType: Mechanical
H7 = CMP-0080604-2: Manufacturer: Alpha Novatech,Inc.; PartNumber: S05MZZ12-B; CompType: Mechanical
LBL = CMP-0003625-1: Thermal Transfer Printable Labels, 0.650" W x 0.200" H - 10,000 per roll; Manufacturer: Brady; CompType: Label
LOGO1 LOGO3 = CMP-0074837-1: IEC 61010-1 Hot Surface Warning; SymbolCreator: a0412235; Lib Reference: IEC_HotSurface
LOGO2 LOGO4 = CMP-0074835-1: IEC 61010-1 High Voltage Warning; SymbolCreator: a0412235; Lib Reference: IEC_HighVoltage
Logo5 = CMP-0074844-1: SymbolCreator: a0412235
Logo6 = CMP-0074838-1: Texas Instrument Corporate Signature; SymbolCreator: a0412235; Lib Reference: TI_Logo; Library Reference: Logo
Logo7 = CMP-0074847-1: FCC_disclaimer; Library Reference: Logo
Logo8 = CMP-0074769-1
ZZ2 = CMP-0077236-1
ZZ3 = CMP-0077237-1
ZZ4 = CMP-0077238-1

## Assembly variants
LMG3422R050: not fitted R2 R3 R10 R12 R17 TH1 TH2 TH3 TH4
